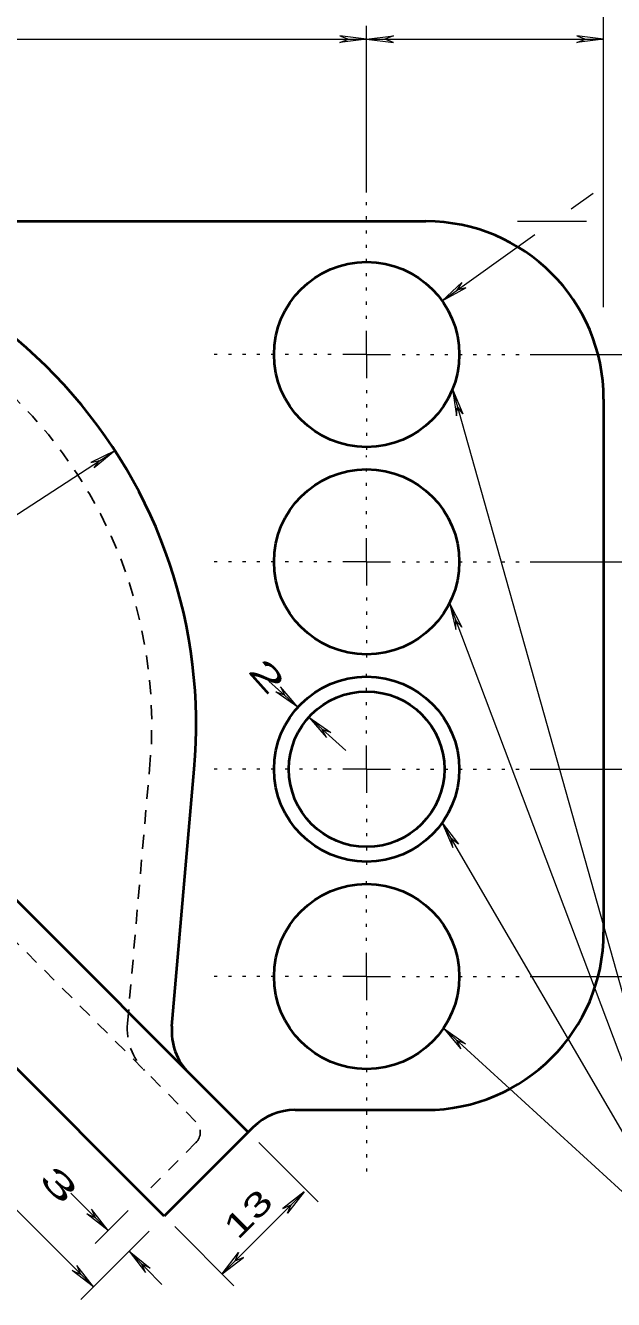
# Model space of a CAD drawing. Extents: x 312583 to 312854, y 144419 to 144597.
# Drawn here: x 312654.99 to 312674.01, y 144447.78 to 144489 of the extents above; entities that cross this region are included whole.
import ezdxf

# ---------------------------------------------------------------- set-up
doc = ezdxf.new("R2010")
doc.units = 0
doc.header["$LTSCALE"] = 0.3
doc.linetypes.add('DOTTED', pattern=[1.5, 0.3, -1.2])
doc.linetypes.add('SHORT_DASHED', pattern=[2.7, 1.5, -1.2])
doc.layers.add('1', color=7, linetype='Continuous', lineweight=40)
doc.layers.add('2', color=7, linetype='Continuous', lineweight=13)

msp = doc.modelspace()

# ---------------------------------------------------------------- linework, layer by layer
at = {"layer": '1'}
for p, q in [((312635.8434, 144482.6609), (312667.9437, 144482.6609)), ((312673.6937, 144476.9109), (312673.6937, 144459.6609)), ((312662.1937, 144453.1902), (312646.776, 144468.6079)), ((312659.4797, 144450.4762), (312643.2187, 144466.7372)), ((312659.725, 144456.6249), (312660.4534, 144464.9356)), ((312663.7117, 144453.9109), (312667.9437, 144453.9109)), ((312662.3547, 144453.3512), (312659.4797, 144450.4762))]:
    msp.add_line(p, q, dxfattribs=at)
at = {"layer": '1', "linetype": 'SHORT_DASHED', "lineweight": 25}
for p, q in [((312660.507, 144453.5276), (312646.27, 144467.7646)), ((312658.2914, 144456.7092), (312659.0044, 144464.9356)), ((312660.507, 144452.8529), (312658.805, 144451.1509))]:
    msp.add_line(p, q, dxfattribs=at)
at = {"layer": '1'}
for centre, radius in [((312666.027, 144478.3522), 2.9948), ((312666.027, 144471.6439), 2.9948), ((312666.027, 144464.9356), 2.9948), ((312666.027, 144464.9356), 2.5156), ((312666.027, 144458.2272), 2.9948)]:
    msp.add_circle(centre, radius, dxfattribs=at)
for centre, radius, start, end in [((312644.223, 144466.3692), 16.2917, 354.95144, 90), ((312667.9437, 144476.9109), 5.75, 0, 90), ((312667.9437, 144459.6609), 5.75, 270, 0), ((312661.6371, 144456.4574), 1.9167, 174.99301, 225.12077), ((312663.7083, 144451.9942), 1.9167, 90, 135)]:
    msp.add_arc(centre, radius, start, end, dxfattribs=at)
at = {"layer": '1', "linetype": 'SHORT_DASHED', "lineweight": 25}
for centre, radius, start, end in [((312644.223, 144466.3692), 14.8542, 354.46141, 90), ((312660.2006, 144456.5446), 1.9167, 175.04383, 225), ((312660.1667, 144453.1902), 0.4792, 315, 45)]:
    msp.add_arc(centre, radius, start, end, dxfattribs=at)
at = {"layer": '2'}
for p, q in [((312673.6937, 144479.8856), (312673.6937, 144491.9452)), ((312666.027, 144483.5886), (312666.027, 144488.9859)), ((312665.1607, 144488.6562), (312665.4367, 144488.5489)), ((312666.027, 144488.5489), (312665.1607, 144488.6562)), ((312665.1607, 144488.4416), (312665.4367, 144488.5489)), ((312666.027, 144488.5489), (312665.1607, 144488.4416)), ((312666.027, 144488.5489), (312666.8934, 144488.6562)), ((312666.027, 144488.5489), (312666.8934, 144488.4416)), ((312666.8934, 144488.6562), (312666.6174, 144488.5489)), ((312666.8934, 144488.4416), (312666.6174, 144488.5489)), ((312672.8274, 144488.6562), (312673.1034, 144488.5489)), ((312673.6937, 144488.5489), (312672.8274, 144488.6562)), ((312672.8274, 144488.4416), (312673.1034, 144488.5489)), ((312673.6937, 144488.5489), (312672.8274, 144488.4416)), ((312672.6434, 144483.0672), (312673.3564, 144483.5732)), ((312670.9107, 144482.6609), (312673.134, 144482.6609)), ((312668.465, 144480.0926), (312671.4704, 144482.2316)), ((312668.465, 144480.0926), (312669.109, 144480.6829)), ((312669.109, 144480.6829), (312668.948, 144480.4376)), ((312668.465, 144480.0926), (312669.2317, 144480.5066)), ((312669.2317, 144480.5066), (312668.948, 144480.4376)), ((312666.027, 144478.3522), (312666.027, 144479.1189)), ((312666.027, 144478.3522), (312665.2604, 144478.3522)), ((312666.027, 144478.3522), (312666.7937, 144478.3522)), ((312666.027, 144478.3522), (312666.027, 144477.5856)), ((312671.317, 144478.3522), (312678.1404, 144478.3522)), ((312668.8024, 144477.2329), (312668.9327, 144476.3666)), ((312668.8024, 144477.2329), (312669.1397, 144476.4279)), ((312668.9327, 144476.3666), (312668.9634, 144476.6656)), ((312669.1397, 144476.4279), (312668.9634, 144476.6656)), ((312644.223, 144466.3692), (312657.885, 144475.2396)), ((312657.885, 144475.2396), (312657.103, 144474.8562)), ((312657.103, 144474.8562), (312657.3867, 144474.9176)), ((312657.885, 144475.2396), (312657.218, 144474.6799)), ((312657.218, 144474.6799), (312657.3867, 144474.9176)), ((312666.027, 144471.6439), (312666.027, 144472.4106)), ((312666.027, 144471.6439), (312665.2604, 144471.6439)), ((312666.027, 144471.6439), (312666.7937, 144471.6439)), ((312666.027, 144471.6439), (312666.027, 144470.8772)), ((312671.317, 144471.6439), (312678.1404, 144471.6439)), ((312668.7027, 144470.3022), (312668.9097, 144469.4512)), ((312668.7027, 144470.3022), (312669.109, 144469.5279)), ((312668.9097, 144469.4512), (312668.9097, 144469.7502)), ((312669.109, 144469.5279), (312668.9097, 144469.7502)), ((312663.8037, 144466.9442), (312662.8684, 144467.7876)), ((312663.2364, 144467.6036), (312663.3667, 144467.3429)), ((312663.8037, 144466.9442), (312663.2364, 144467.6036)), ((312663.0907, 144467.4426), (312663.3667, 144467.3429)), ((312663.8037, 144466.9442), (312663.0907, 144467.4426)), ((312665.3524, 144465.5412), (312664.1564, 144466.6222)), ((312664.1564, 144466.6222), (312664.7237, 144465.9629)), ((312664.1564, 144466.6222), (312664.8694, 144466.1239)), ((312664.7237, 144465.9629), (312664.5934, 144466.2236)), ((312664.8694, 144466.1239), (312664.5934, 144466.2236)), ((312666.027, 144464.9356), (312666.027, 144465.7022)), ((312666.027, 144464.9356), (312665.2604, 144464.9356)), ((312666.027, 144464.9356), (312666.7937, 144464.9356)), ((312666.027, 144464.9356), (312666.027, 144464.1689)), ((312671.317, 144464.9356), (312678.1404, 144464.9356)), ((312657.1874, 144448.1839), (312640.9264, 144464.4449)), ((312676.7374, 144449.0272), (312668.465, 144463.2029)), ((312668.465, 144463.2029), (312668.81, 144462.3979)), ((312668.465, 144463.2029), (312668.994, 144462.5052)), ((312668.81, 144462.3979), (312668.764, 144462.6969)), ((312668.994, 144462.5052), (312668.764, 144462.6969)), ((312666.027, 144458.2272), (312666.027, 144458.9939)), ((312666.027, 144458.2272), (312665.2604, 144458.2272)), ((312666.027, 144458.2272), (312666.7937, 144458.2272)), ((312666.027, 144458.2272), (312666.027, 144457.4606)), ((312671.317, 144458.2272), (312678.1404, 144458.2272)), ((312676.7374, 144449.0272), (312668.511, 144456.5559)), ((312668.511, 144456.5559), (312669.0784, 144455.8889)), ((312668.511, 144456.5559), (312669.224, 144456.0499)), ((312669.0784, 144455.8889), (312668.948, 144456.1572)), ((312669.224, 144456.0499), (312668.948, 144456.1572)), ((312662.5387, 144452.8529), (312664.463, 144450.9362)), ((312657.6627, 144450.0086), (312656.459, 144451.2199)), ((312661.3504, 144448.6056), (312664.003, 144451.2582)), ((312664.003, 144451.2582), (312663.313, 144450.7216)), ((312664.003, 144451.2582), (312663.4664, 144450.5682)), ((312656.9727, 144450.5452), (312657.2487, 144450.4302)), ((312657.6627, 144450.0086), (312656.9727, 144450.5452)), ((312657.126, 144450.6986), (312657.2487, 144450.4302)), ((312657.6627, 144450.0086), (312657.126, 144450.6986)), ((312658.3144, 144450.6602), (312657.2487, 144449.5946)), ((312663.313, 144450.7216), (312663.589, 144450.8442)), ((312663.4664, 144450.5682), (312663.589, 144450.8442)), ((312659.8247, 144450.1389), (312661.7337, 144448.2222)), ((312658.989, 144449.9856), (312656.781, 144447.7776)), ((312659.403, 144448.2682), (312658.345, 144449.3416)), ((312658.345, 144449.3416), (312658.874, 144448.6516)), ((312658.345, 144449.3416), (312659.0274, 144448.7972)), ((312658.874, 144448.6516), (312658.759, 144448.9199)), ((312659.0274, 144448.7972), (312658.759, 144448.9199)), ((312661.3504, 144448.6056), (312661.887, 144449.2956)), ((312661.3504, 144448.6056), (312662.0404, 144449.1422)), ((312661.887, 144449.2956), (312661.7644, 144449.0196)), ((312662.0404, 144449.1422), (312661.7644, 144449.0196)), ((312656.4974, 144448.7206), (312656.7734, 144448.5979)), ((312657.1874, 144448.1839), (312656.4974, 144448.7206)), ((312656.6507, 144448.8739), (312656.7734, 144448.5979)), ((312657.1874, 144448.1839), (312656.6507, 144448.8739))]:
    msp.add_line(p, q, dxfattribs=at)
at = {"layer": '2', "linetype": 'DOTTED'}
for p, q in [((312666.027, 144479.5022), (312666.027, 144483.5886)), ((312664.877, 144478.3522), (312660.8597, 144478.3522)), ((312667.177, 144478.3522), (312671.317, 144478.3522)), ((312666.027, 144477.2022), (312666.027, 144475.0786)), ((312666.027, 144472.7249), (312666.027, 144475.0786)), ((312664.877, 144471.6439), (312660.8597, 144471.6439)), ((312667.177, 144471.6439), (312671.317, 144471.6439)), ((312666.027, 144470.4939), (312666.027, 144468.2706)), ((312666.027, 144466.0856), (312666.027, 144468.2706)), ((312664.877, 144464.9356), (312660.8597, 144464.9356)), ((312667.177, 144464.9356), (312671.317, 144464.9356)), ((312666.027, 144463.7856), (312666.027, 144461.5546)), ((312666.027, 144459.3772), (312666.027, 144461.5546)), ((312664.877, 144458.2272), (312660.8597, 144458.2272)), ((312667.177, 144458.2272), (312671.317, 144458.2272)), ((312666.027, 144457.0772), (312666.027, 144451.9022))]:
    msp.add_line(p, q, dxfattribs=at)
at = {"layer": '2'}
for points in [[(312621.9437, 144488.5489), (312639.1937, 144488.5489), (312666.027, 144488.5489), (312673.6937, 144488.5489)], [(312668.8024, 144477.2329), (312676.7374, 144449.0272), (312668.7027, 144470.3022)]]:
    msp.add_lwpolyline(points, dxfattribs=at)

# ---------------------------------------------------------------- texts
for s, rotation, width, p in [('2', 311.798, 1.95, (312662.1502, 144468.0995)), ('3', 315, 2.1, (312655.3906, 144451.6458)), ('13', 45, 1.5, (312661.8612, 144449.6842))]:
    msp.add_text(s, height=0.76, rotation=rotation, dxfattribs=dict(at, width=width)).set_placement(p)

doc.saveas('drawing.dxf')
